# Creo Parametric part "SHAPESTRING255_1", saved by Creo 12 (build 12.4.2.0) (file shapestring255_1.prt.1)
Units: Custom; MM, KILOGRAM, SECS

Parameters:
  PTC_WM_ITERATION = "0"
  PTC_WM_VERSION = "-.0"
  PTC_WM_LIFECYCLE_STATE = "In Work"
  PTC_WM_LIFECYCLE = "MO_CADDocument"
  PTC_WM_CREATED_BY = "Maximilian Roepper (Z0017RMS: MO)"
  PTC_WM_CREATED_ON = "18-Sep-26 11:36:42 AM"
  PTC_WM_MODIFIED_BY = "Maximilian Roepper (Z0017RMS: MO)"
  PTC_WM_MODIFIED_ON = "18-Sep-26 11:36:46 AM"
  PDMLINKNUMBER = "PDM000071455011"
  PTC_WM_NAME = "shapestring255_1.prt"
  PTC_WM_NUMBER = "PDM000071455011"

Other parameters: WEIGHT, WEIGHT_FACTOR, WEIGHT_ADD, _MASS_TEMP, _DIFF_TEMP, MC_ERRORS, SUPPLIER

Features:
  1. coordinate system
  2. datum plane "PRT_YZ"
  3. datum plane "PRT_XY"
  4. datum plane "PRT_XZ"
  5. coordinate system
  6. datum axis
  7. datum axis
  8. datum axis
  9. coordinate system
  10. imported feature
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
Other named items: PRT, SIEMENS_MO, DRW_VIEW_ORG, PRT_X, PRT_Y, PRT_Z, CS0, ROUGH_GROB

Layers: 00_STD_CSYS-KSYS, 01_STD_PLANES-EBENEN, 02_STD_AXES-ACHSEN, 03_STD_CSYS-KSYS, 24_IMPORT_FEAT-IMPORT_KE, WHITE

Surfaces: 1 plane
